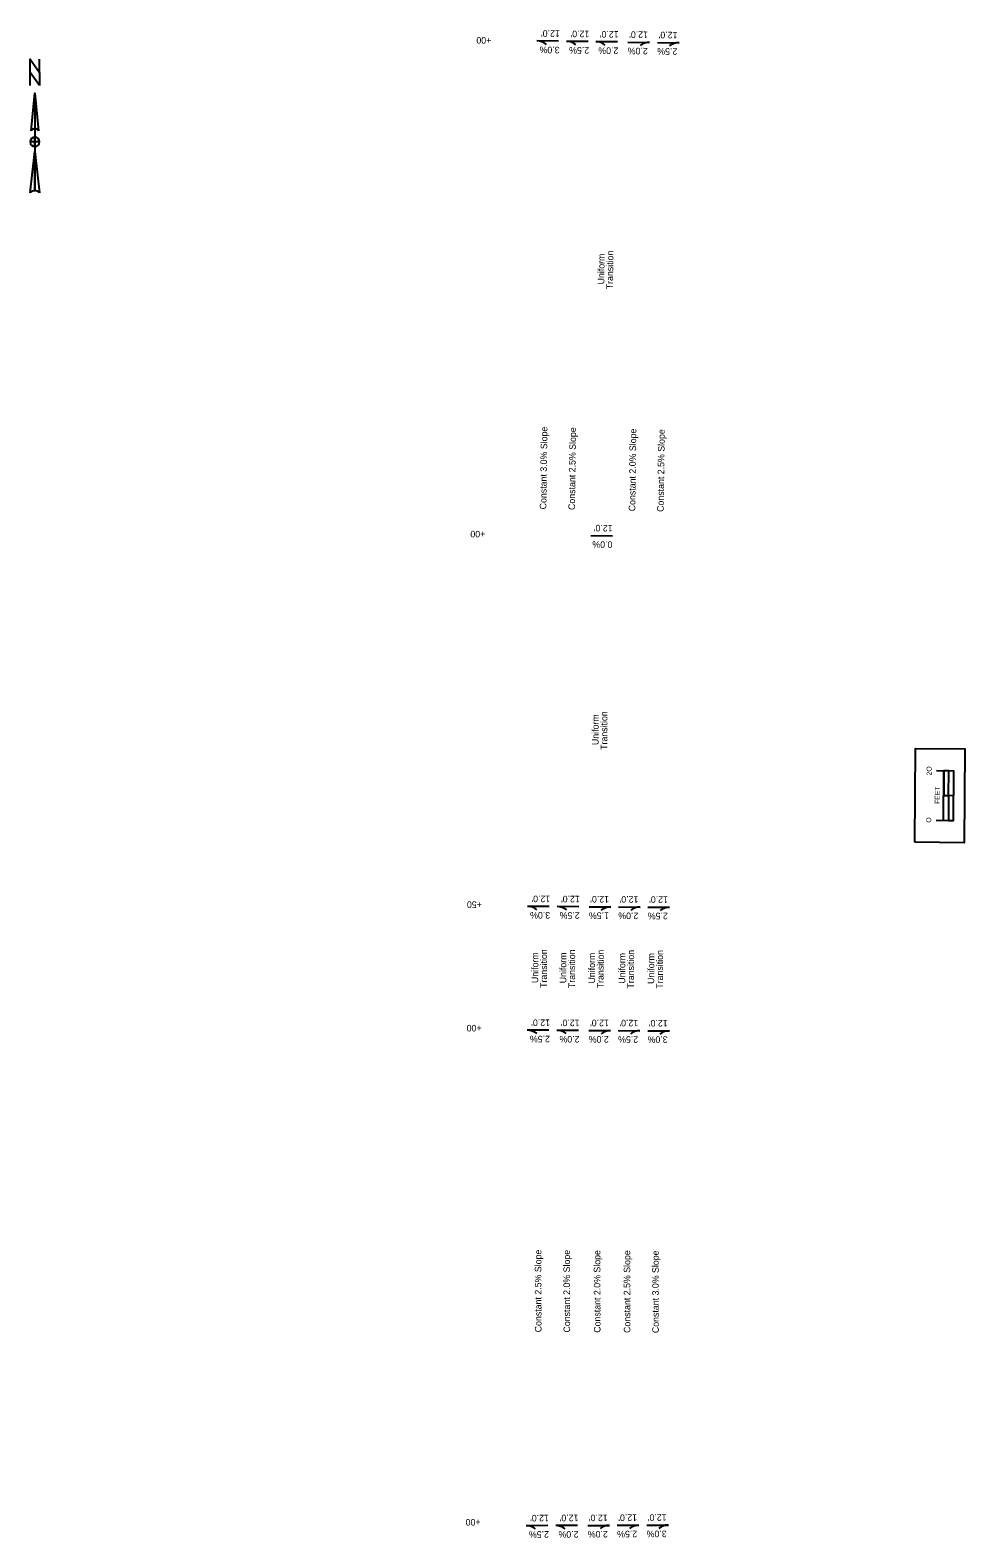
# Model space of a CAD drawing. Extents: x 20505195 to 20506806, y 7965197 to 7979043.
# Drawn here: x 20506333 to 20506711, y 7965197 to 7965807 of the extents above; entities that cross this region are included whole.
import ezdxf

# ---------------------------------------------------------------- set-up
doc = ezdxf.new("R2010")
doc.units = 0
doc.layers.add('Cell', color=7, linetype='Continuous')
doc.layers.add('SheetText', color=7, linetype='Continuous')

msp = doc.modelspace()

# ---------------------------------------------------------------- linework, layer by layer
at = {"layer": 'Cell'}
for p, q in [((20506334.98, 7965781.7), (20506336.5, 7965766.48)), ((20506334.98, 7965781.7), (20506334.98, 7965742.14)), ((20506333.46, 7965766.48), (20506333.46, 7965766.48)), ((20506333.52, 7965766.62), (20506333.8, 7965766.94)), ((20506333.08, 7965741.38), (20506334.98, 7965758.12)), ((20506334.98, 7965760.02), (20506334.98, 7965760.02))]:
    msp.add_line(p, q, dxfattribs=at)
msp.add_lwpolyline([(20506336.88, 7965784.74), (20506333.08, 7965790.06), (20506333.08, 7965795.39), (20506336.88, 7965790.06)], close=True, dxfattribs=at)
for points in [[(20506333.08, 7965784.74), (20506333.08, 7965795.39), (20506336.88, 7965790.06), (20506336.88, 7965795.39)], [(20506333.46, 7965766.48), (20506334.98, 7965781.7), (20506334.98, 7965767.24)], [(20506336.88, 7965761.92), (20506334.98, 7965761.92), (20506334.98, 7965763.82)], [(20506334.98, 7965760.02), (20506334.98, 7965761.92), (20506333.08, 7965761.92)], [(20506334.98, 7965742.14), (20506334.98, 7965758.12), (20506336.88, 7965741.38)]]:
    msp.add_lwpolyline(points, dxfattribs=at)
for centre, radius, start, end in [((20506334.98, 7965761.92), 1.9, 90, 180), ((20506334.98, 7965765.34), 1.9, 90.02039, 143.12574), ((20506334.98, 7965765.34), 1.9, 36.84806, 90.02184), ((20506334.98, 7965761.92), 1.9, 0, 90), ((20506334.98, 7965761.92), 1.9, 180, 270), ((20506334.98, 7965761.92), 1.9, 270, 360), ((20506334.98, 7965739.39), 2.76, 89.98939, 133.61895), ((20506334.98, 7965739.39), 2.76, 46.40206, 90.00064)]:
    msp.add_arc(centre, radius, start, end, dxfattribs=at)
at = {"layer": 'SheetText'}
for p, q in [((20506546.98, 7965802.7), (20506538.21, 7965802.81)), ((20506558.94, 7965802.55), (20506550.17, 7965802.66)), ((20506570.78, 7965802.4), (20506562.01, 7965802.51)), ((20506575.03, 7965802.35), (20506583.8, 7965802.24)), ((20506586.97, 7965802.2), (20506595.74, 7965802.09)), ((20506559.98, 7965602.52), (20506568.75, 7965602.41)), ((20506706.84, 7965497.17), (20506702.84, 7965497.2)), ((20506706.84, 7965497.17), (20506702.84, 7965497.2)), ((20506543.13, 7965452.3), (20506534.36, 7965452.36)), ((20506555.1, 7965452.23), (20506546.33, 7965452.28)), ((20506559.3, 7965452.2), (20506568.07, 7965452.15)), ((20506571.19, 7965452.13), (20506579.96, 7965452.07)), ((20506583.12, 7965452.05), (20506591.9, 7965452)), ((20506543.05, 7965402.16), (20506534.28, 7965402.2)), ((20506555.02, 7965402.11), (20506546.25, 7965402.15)), ((20506559.22, 7965402.09), (20506567.99, 7965402.06)), ((20506571.11, 7965402.04), (20506579.88, 7965402.01)), ((20506583.05, 7965401.99), (20506591.82, 7965401.96)), ((20506570.68, 7965201.71), (20506579.45, 7965201.75)), ((20506582.62, 7965201.76), (20506591.39, 7965201.8)), ((20506542.63, 7965201.58), (20506533.85, 7965201.54)), ((20506554.59, 7965201.63), (20506545.82, 7965201.59)), ((20506558.79, 7965201.65), (20506567.56, 7965201.69))]:
    msp.add_line(p, q, dxfattribs=at)
for points in [[(20506691.1, 7965478.29), (20506691.38, 7965516.29), (20506711.38, 7965516.14), (20506711.1, 7965478.14)], [(20506691.1, 7965478.29), (20506691.38, 7965516.29), (20506711.38, 7965516.14), (20506711.1, 7965478.14)], [(20506704.83, 7965497.19), (20506704.9, 7965507.19), (20506702.91, 7965507.2), (20506702.84, 7965497.2)], [(20506706.77, 7965487.17), (20506706.84, 7965497.17), (20506704.83, 7965497.19), (20506704.75, 7965487.19)]]:
    msp.add_lwpolyline(points, close=True, dxfattribs=at)
for points in [[(20506699.77, 7965487.23), (20506706.77, 7965487.17), (20506706.91, 7965507.17), (20506699.91, 7965507.23)], [(20506702.77, 7965487.2), (20506702.91, 7965507.2)]]:
    msp.add_lwpolyline(points, dxfattribs=at)
for centre, start, end in [((20506538.13, 7965796.65), 51.07602, 89.27906), ((20506550.1, 7965796.5), 51.07602, 89.27906), ((20506561.94, 7965796.35), 51.07602, 89.27906), ((20506583.72, 7965796.07), 89.27906, 127.4821), ((20506595.66, 7965795.92), 89.27906, 127.4821), ((20506534.32, 7965446.2), 51.43535, 89.63839), ((20506546.29, 7965446.12), 51.43535, 89.63839), ((20506568.03, 7965445.98), 89.63839, 127.84142), ((20506579.92, 7965445.91), 89.63839, 127.84142), ((20506591.86, 7965445.83), 89.63839, 127.84142), ((20506534.26, 7965396.03), 51.56035, 89.76339), ((20506546.22, 7965395.98), 51.56035, 89.76339), ((20506567.96, 7965395.89), 89.76339, 127.96642), ((20506579.85, 7965395.84), 89.76339, 127.96642), ((20506591.79, 7965395.79), 89.76339, 127.96642), ((20506579.48, 7965195.58), 90.26339, 128.46642), ((20506591.42, 7965195.64), 90.26339, 128.46642), ((20506533.88, 7965195.37), 52.06035, 90.26339), ((20506545.85, 7965195.43), 52.06035, 90.26339), ((20506567.59, 7965195.53), 90.26339, 128.46642)]:
    msp.add_arc(centre, 6.16, start, end, dxfattribs=at)

# ---------------------------------------------------------------- texts
for s, height, rotation, p in [("12.0'", 2.664, 179.38178, (20506547.47, 7965807.09)), ("12.0'", 2.664, 179.38178, (20506559.43, 7965806.94)), ("12.0'", 2.664, 179.38178, (20506571.27, 7965806.79)), ("12.0'", 2.664, 179.38178, (20506583.16, 7965806.64)), ("12.0'", 2.664, 179.38178, (20506595.1, 7965806.49)), ('+00', 2.664, 179.38178, (20506519.74, 7965804.38)), ('3.0%', 2.664, 179.38178, (20506547.38, 7965800.47)), ('2.5%', 2.664, 179.38178, (20506559.35, 7965800.32)), ('2.0%', 2.664, 179.38178, (20506571.18, 7965800.17)), ('2.0%', 2.664, 179.38178, (20506583.07, 7965800.02)), ('2.5%', 2.664, 179.38178, (20506595.01, 7965799.87)), ('Uniform', 2.664, 89.29049, (20506565.44, 7965704.22)), ('Transition', 2.664, 89.29049, (20506568.96, 7965702.25)), ('Constant 3.0% Slope', 2.664, 89.2393, (20506542, 7965613.12)), ('Constant 2.5% Slope', 2.664, 89.2393, (20506553.58, 7965612.87)), ('Constant 2.0% Slope', 2.664, 89.2393, (20506577.98, 7965612.34)), ('Constant 2.5% Slope', 2.664, 89.2393, (20506589.49, 7965612.09)), ("12.0'", 2.664, 179.38178, (20506568.84, 7965606.81)), ('+00', 2.664, 179.38178, (20506517.31, 7965604.4)), ('0.0%', 2.664, 179.38178, (20506568.75, 7965600.18)), ('Uniform', 2.664, 89.75693, (20506563.13, 7965517.65)), ('Transition', 2.664, 89.75693, (20506566.66, 7965515.72)), ('2O', 2, 89.57924, (20506697.9, 7965505.37)), ('FEET', 2, 89.57924, (20506701.21, 7965493.83)), ('O', 2, 89.57924, (20506697.76, 7965486.26)), ('+50', 2.664, 179.74111, (20506515.89, 7965454.37)), ("12.0'", 2.664, 179.74111, (20506543.59, 7965456.7)), ("12.0'", 2.664, 179.74111, (20506555.56, 7965456.62)), ("12.0'", 2.664, 179.74111, (20506567.4, 7965456.55)), ("12.0'", 2.664, 179.74111, (20506579.28, 7965456.47)), ("12.0'", 2.664, 179.74111, (20506591.22, 7965456.4)), ('3.0%', 2.664, 179.74111, (20506543.55, 7965450.07)), ('2.5%', 2.664, 179.74111, (20506555.51, 7965450)), ('1.5%', 2.664, 179.74111, (20506567.35, 7965449.92)), ('2.0%', 2.664, 179.74111, (20506579.24, 7965449.85)), ('2.5%', 2.664, 179.74111, (20506591.18, 7965449.77)), ('Transition', 2.664, 89.75693, (20506542.23, 7965419.33)), ('Transition', 2.664, 89.75693, (20506553.6, 7965419.25)), ('Transition', 2.664, 89.75693, (20506565.2, 7965419.17)), ('Transition', 2.664, 89.75693, (20506577.47, 7965419.09)), ('Transition', 2.664, 89.75693, (20506589.18, 7965419.01)), ('Uniform', 2.664, 89.75693, (20506538.69, 7965421.27)), ('Uniform', 2.664, 89.75693, (20506550.07, 7965421.19)), ('Uniform', 2.664, 89.75693, (20506561.67, 7965421.11)), ('Uniform', 2.664, 89.75693, (20506573.93, 7965421.03)), ('Uniform', 2.664, 89.75693, (20506585.65, 7965420.94)), ('+00', 2.664, 179.86611, (20506515.8, 7965404.35)), ("12.0'", 2.664, 179.86611, (20506543.5, 7965406.55)), ("12.0'", 2.664, 179.86611, (20506555.47, 7965406.5)), ("12.0'", 2.664, 179.86611, (20506567.31, 7965406.45)), ("12.0'", 2.664, 179.86611, (20506579.2, 7965406.4)), ("12.0'", 2.664, 179.86611, (20506591.13, 7965406.36)), ('2.5%', 2.664, 179.86611, (20506543.47, 7965399.93)), ('2.0%', 2.664, 179.86611, (20506555.44, 7965399.88)), ('2.0%', 2.664, 179.86611, (20506567.28, 7965399.83)), ('2.5%', 2.664, 179.86611, (20506579.17, 7965399.78)), ('3.0%', 2.664, 179.86611, (20506591.1, 7965399.73)), ('Constant 2.5% Slope', 2.664, 90.08773, (20506540.04, 7965279.86)), ('Constant 2.0% Slope', 2.664, 90.08773, (20506551.62, 7965279.78)), ('Constant 2.0% Slope', 2.664, 90.08773, (20506563.92, 7965279.69)), ('Constant 2.5% Slope', 2.664, 90.08773, (20506576.02, 7965279.61)), ('Constant 3.0% Slope', 2.664, 90.08773, (20506587.53, 7965279.53)), ('+00', 2.664, 180.36611, (20506515.37, 7965204.3)), ("12.0'", 2.664, 180.36611, (20506543.04, 7965205.97)), ("12.0'", 2.664, 180.36611, (20506555, 7965206.03)), ("12.0'", 2.664, 180.36611, (20506566.84, 7965206.08)), ("12.0'", 2.664, 180.36611, (20506578.73, 7965206.14)), ("12.0'", 2.664, 180.36611, (20506590.67, 7965206.19)), ('2.5%', 2.664, 180.36611, (20506543.06, 7965199.35)), ('2.0%', 2.664, 180.36611, (20506555.03, 7965199.4)), ('2.0%', 2.664, 180.36611, (20506566.87, 7965199.46)), ('2.5%', 2.664, 180.36611, (20506578.76, 7965199.51)), ('3.0%', 2.664, 180.36611, (20506590.7, 7965199.57))]:
    msp.add_text(s, height=height, rotation=rotation, dxfattribs=at).set_placement(p)

doc.saveas('drawing.dxf')
